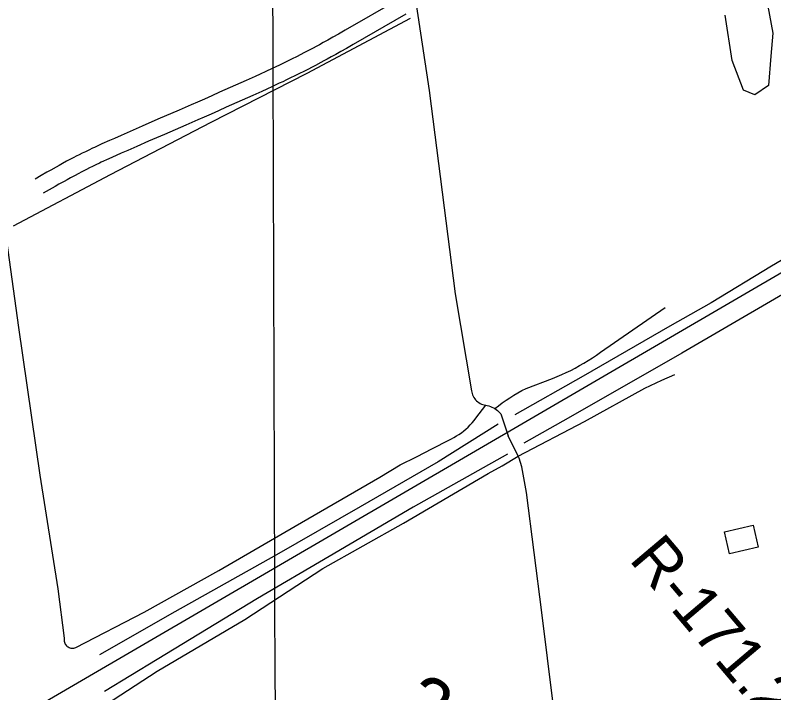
# Model space of a CAD drawing. Extents: x 3392644 to 3430565, y 576657 to 602123.
# Drawn here: x 3401526 to 3402912, y 596309 to 597547 of the extents above; entities that cross this region are included whole.
import ezdxf

# ---------------------------------------------------------------- set-up
doc = ezdxf.new("R2010")
doc.units = 0
for name, color, linetype in [('V-BLDG-OTLN', 7, 'Continuous'), ('V-DTCH-CNTR', 7, 'Continuous'), ('V-GRID-MAJR', 7, 'Continuous'), ('V-RIVR-RANG-IDEN', 7, 'Continuous'), ('V-ROAD-CNTR', 7, 'Continuous'), ('V-SITE-VEGE', 7, 'Continuous'), ('V-SURV-IDEN', 7, 'Continuous'), ('V-TOPO-SHOR', 7, 'Continuous')]:
    doc.layers.add(name, color=color, linetype=linetype)

msp = doc.modelspace()

# ---------------------------------------------------------------- linework, layer by layer
at = {"layer": 'V-BLDG-OTLN'}
msp.add_lwpolyline([(3402821.531, 596603.055), (3402874.046, 596615.425), (3402883.5670000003, 596575.002), (3402831.054, 596562.632)], close=True, dxfattribs=at)
at = {"layer": 'V-DTCH-CNTR'}
for points in [[(3402253.3170000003, 597599.637), (3402281.94, 597409.752), (3402329.599, 597038.108), (3402359.6, 596860.853), (3402360.024, 596858.258), (3402360.671, 596855.709), (3402361.536, 596853.2220000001), (3402362.609, 596850.8200000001), (3402363.883, 596848.518), (3402365.3510000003, 596846.335), (3402367, 596844.287), (3402368.8200000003, 596842.386), (3402370.7970000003, 596840.65), (3402372.912, 596839.087), (3402375.157, 596837.715), (3402377.5100000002, 596836.537), (3402379.955, 596835.569), (3402382.474, 596834.813), (3402385.43, 596834.465), (3402388.356, 596833.916), (3402391.238, 596833.166), (3402394.0640000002, 596832.2220000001), (3402396.8170000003, 596831.09), (3402399.487, 596829.769), (3402402.059, 596828.27), (3402404.525, 596826.596), (3402406.87, 596824.759), (3402409.0840000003, 596822.767), (3402411.159, 596820.629), (3402413.08, 596818.353), (3402426.75, 596778.53)], [(3401504.747, 597170.916), (3401531.893, 596976.463), (3401570.887, 596706.453), (3401603.759, 596499.0700000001), (3401615.058, 596408.514), (3401614.87, 596406.666), (3401614.9, 596404.811), (3401615.148, 596402.97), (3401615.613, 596401.174), (3401616.287, 596399.443), (3401617.157, 596397.805), (3401618.218, 596396.281), (3401619.449, 596394.89), (3401620.838, 596393.657), (3401622.359, 596392.594), (3401623.998, 596391.7220000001), (3401625.7260000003, 596391.044), (3401627.522, 596390.577), (3401629.361, 596390.327), (3401631.219, 596390.295), (3401633.066, 596390.481), (3401634.879, 596390.882), (3401636.63, 596391.497), (3401761.451, 596456.199), (3401897.537, 596532.129), (3402037.4760000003, 596613.639), (3402191.892, 596702.877), (3402229.0100000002, 596725.556), (3402258.757, 596740.355), (3402288.3710000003, 596755.422), (3402317.846, 596770.756), (3402322.691, 596773.031), (3402327.432, 596775.515), (3402332.063, 596778.202), (3402336.571, 596781.09), (3402340.949, 596784.1680000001), (3402345.191, 596787.435), (3402349.284, 596790.881), (3402353.227, 596794.504), (3402357.008, 596798.2930000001), (3402360.62, 596802.2440000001), (3402364.059, 596806.346), (3402367.315, 596810.593), (3402385.43, 596834.465)], [(3402402.059, 596828.27), (3402408.789, 596833.474), (3402415.64, 596838.5160000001), (3402422.611, 596843.39), (3402429.697, 596848.096), (3402436.896, 596852.631), (3402444.199, 596856.991), (3402451.607, 596861.175), (3402459.113, 596865.179), (3402507.705, 596883.201), (3402516.131, 596886.6460000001), (3402524.477, 596890.281), (3402532.736, 596894.101), (3402540.91, 596898.106), (3402548.991, 596902.295), (3402556.9760000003, 596906.6630000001), (3402564.859, 596911.212), (3402572.639, 596915.934), (3402580.311, 596920.833), (3402587.872, 596925.902), (3402595.315, 596931.1410000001), (3402713.552, 597013.098)], [(3402444.91, 596741.029), (3402566.133, 596804.458), (3402675.963, 596865.34), (3402707.267, 596880.426), (3402731.163, 596890.267)], [(3402628.8140000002, 595392.3), (3402605.93, 595542.554), (3402577.204, 595762.898), (3402548.467, 595984.031), (3402518.472, 596209.8740000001), (3402487.764, 596455.814), (3402459.852, 596674.596), (3402451.613, 596721.78), (3402446.632, 596737.4720000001), (3402444.91, 596741.029), (3402426.75, 596778.53)], [(3401664.687, 596269.686), (3401785.273, 596348.481), (3401945.04, 596442.879), (3402087.876, 596535.83), (3402235.203, 596618.991), (3402389.9, 596709.762), (3402415.705, 596723.576), (3402444.91, 596741.029)]]:
    msp.add_lwpolyline(points, dxfattribs=at)
at = {"layer": 'V-GRID-MAJR'}
msp.add_spline([(3402048.6720000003, 582063.4890000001), (3402028.4020000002, 588122.6730000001), (3402008.125, 594183.791), (3401987.849, 600244.93), (3401987.843, 600246.845)], degree=3, dxfattribs=at)
at = {"layer": 'V-ROAD-CNTR'}
for points in [[(3406286.472389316, 599035.916901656), (3400804.722352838, 595840.678292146), (3396739.40448349, 593474.059025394)], [(3402224.2815137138, 597575.034823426), (3402128.37370553, 597519.4159346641), (3402116.406729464, 597512.5909483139), (3402105.9017504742, 597506.659960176), (3402096.694768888, 597501.515970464), (3402088.6237850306, 597497.053979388), (3402081.550799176, 597493.1829871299), (3402075.350811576, 597489.8209938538), (3402069.92882242, 597486.9079996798), (3402060.3848415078, 597481.8440098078), (3402053.2188558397, 597478.0980172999), (3402047.8448665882, 597475.3220228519), (3402039.7378828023, 597471.190031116), (3402031.60889906, 597467.1180392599), (3402023.470915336, 597463.110047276), (3402015.814930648, 597459.3930547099), (3402008.617945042, 597455.94306161), (3402001.8509585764, 597452.7330680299), (3401995.5039712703, 597449.7500739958), (3401983.5389952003, 597444.195085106), (3401973.047016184, 597439.3820947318), (3401963.8510345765, 597435.2011030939), (3401947.69406689, 597427.920117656), (3401899.062164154, 597406.1511611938), (3401884.845192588, 597399.7871739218), (3401871.5182192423, 597393.8721857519), (3401859.0052442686, 597388.3561967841), (3401847.2482677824, 597383.2022070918)], [(3402239.30348367, 597549.066875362), (3402143.329675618, 597493.409986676), (3402131.212699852, 597486.4990004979), (3402120.591721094, 597480.504012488), (3402111.2687397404, 597475.294022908), (3402103.08375611, 597470.76803196), (3402095.9007704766, 597466.8370398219), (3402089.59878308, 597463.421046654), (3402084.05879416, 597460.444052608), (3402074.364813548, 597455.300062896), (3402067.0528281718, 597451.47807054), (3402061.540839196, 597448.630076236), (3402053.267855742, 597444.4140846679), (3402044.954872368, 597440.2500929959), (3402036.64888898, 597436.160101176), (3402028.8509045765, 597432.3731087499), (3402021.5299192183, 597428.8631157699), (3402014.65893296, 597425.6051222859), (3402008.2019458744, 597422.570128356), (3401996.110970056, 597416.955139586), (3401985.50899126, 597412.092149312), (3401976.221009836, 597407.871157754), (3401959.986042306, 597400.5541723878), (3401911.320139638, 597378.7692159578), (3401897.05916816, 597372.385228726), (3401883.65419497, 597366.4362406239), (3401871.077220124, 597360.8922517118), (3401859.2922436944, 597355.7262620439)], [(3401847.276267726, 597383.214207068), (3401825.1993118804, 597373.590226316), (3401786.5183892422, 597356.8152598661), (3401757.4864473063, 597344.205285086), (3401735.711490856, 597334.6863041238), (3401719.3885235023, 597327.495318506), (3401707.1515479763, 597322.064329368), (3401697.97456633, 597317.96333757), (3401684.231593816, 597311.776349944), (3401670.498621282, 597305.527362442), (3401666.9626283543, 597303.897365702), (3401660.188641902, 597300.710372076), (3401653.857654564, 597297.6573781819), (3401647.9546663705, 597294.750383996), (3401642.44467739, 597291.9853895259), (3401637.303687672, 597289.36339477), (3401632.5036972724, 597286.880399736), (3401628.002706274, 597284.5234044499), (3401619.647722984, 597280.0764133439), (3401612.3607375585, 597276.129421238), (3401606.008750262, 597272.64342821), (3401600.4617613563, 597269.5674343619), (3401590.8197806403, 597264.160445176), (3401583.5997950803, 597260.067453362), (3401572.8218166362, 597253.9114656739), (3401562.07983812, 597247.736478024)], [(3401859.2642437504, 597355.714262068), (3401837.1612879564, 597346.0782813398), (3401798.462365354, 597329.2953149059), (3401769.470423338, 597316.7033400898), (3401747.7674667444, 597307.2163590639), (3401731.5204992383, 597300.0573733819), (3401719.355523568, 597294.6583841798), (3401710.2505417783, 597290.591392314), (3401696.6035690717, 597284.446404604), (3401682.990596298, 597278.2514169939), (3401679.628603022, 597276.701420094), (3401673.0886161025, 597273.6244262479), (3401666.9996282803, 597270.689432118), (3401661.308639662, 597267.8864377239), (3401655.988650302, 597265.2174430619), (3401651.0116602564, 597262.6774481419), (3401646.353669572, 597260.2684529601), (3401642.010678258, 597257.99345751), (3401633.8396946, 597253.644466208), (3401626.720708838, 597249.7894739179), (3401620.500721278, 597246.375480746), (3401615.073732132, 597243.3654867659), (3401605.553751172, 597238.0264974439), (3401598.435765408, 597233.9935055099), (3401587.7377868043, 597227.8815177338), (3401577.02980822, 597221.7265300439)]]:
    msp.add_lwpolyline(points, dxfattribs=at)
at = {"layer": 'V-SITE-VEGE'}
msp.add_lwpolyline([(3402897.835, 597580.355), (3402910.281, 597513.934), (3402906.132, 597472.419), (3402901.982, 597418.452), (3402877.095, 597401.8470000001), (3402856.355, 597410.149), (3402835.615, 597464.116), (3402823.167, 597547.142)], dxfattribs=at)
at = {"layer": 'V-TOPO-SHOR'}
msp.add_line((3401785.302, 596369.866), (3401688.702, 596311.313), dxfattribs=at)
for points in [[(3402247.6550000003, 597541.309), (3402058.663, 597440.263), (3401882.879, 597350.845), (3401699.313, 597255.398), (3401522.022, 597161.627)], [(3402997.882, 597141.583), (3402907.758, 597088.568), (3402797.381, 597021.451), (3402721.66, 596978.904), (3402563.235, 596887.399), (3402438.739, 596816.514)], [(3402997.4990000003, 597077.632), (3402744.045, 596929.756), (3402535.855, 596810.581), (3402454.994, 596764.761)], [(3402408.289, 596799.888), (3402298.336, 596730.809), (3402155.9080000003, 596648.615), (3402002.937, 596560.7390000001), (3401817.542, 596456.601), (3401679.781, 596378.025)], [(3402425.353, 596744.979), (3402253.074, 596648.052), (3402099.603, 596558.12), (3401968.389, 596481.154), (3401785.302, 596369.866)]]:
    msp.add_lwpolyline(points, dxfattribs=at)

# ---------------------------------------------------------------- texts
at = {"layer": 'V-RIVR-RANG-IDEN'}
msp.add_text('R-171.2', height=82.9999980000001, rotation=310.21774294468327, dxfattribs=at).set_placement((3402645.688507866, 596551.9109601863))
at = {"layer": 'V-SURV-IDEN'}
msp.add_text('2908+06.7', height=100.00000000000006, rotation=326.5955268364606, dxfattribs=at).set_placement((3402218.284355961, 596266.7475698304))

doc.saveas('drawing.dxf')
